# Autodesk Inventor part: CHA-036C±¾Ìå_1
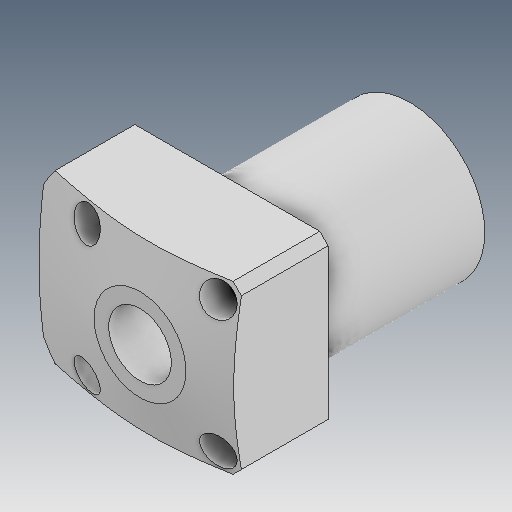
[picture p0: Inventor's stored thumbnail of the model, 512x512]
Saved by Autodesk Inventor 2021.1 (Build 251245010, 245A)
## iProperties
Created: 2019-12
Part Number: CHA-036C±¾Ìå_1
Material: Ogólny
Document SubType Name: Modeling
Designer: user
Density: 1 g/cm^3
Appearance: Domyślna
Author: user
Revision Number: ÈÎºÎ
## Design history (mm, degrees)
feature "NONE"
node "Bryła1"
